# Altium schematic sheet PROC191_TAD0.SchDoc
size 431 x 279 mm; Date: Not shown in title block; ApprovedBy: Not shown in title block; CheckedBy: Not shown in title block; Author: Not shown in title block; CompanyName: Not shown in title block; Engineer: Not shown in title block; Organization: Not shown in title block; Address1: Not shown in title block; Address2: Not shown in title block; Address3: Not shown in title block; Address4: Not shown in title block; DocumentNumber: 4; Revision: Use project parameter SCH_Rev; SheetNumber: 6; SheetTotal: 8; PageSetup: Record=PageOptions¦CenterHorizontal=True¦CenterVertical=True¦PrintScale=1.00¦XCorrection=1.00¦YCorrection=1.00¦PrintKind=0¦BorderSize=5000000¦LeftOffset=0¦BottomOffset=0¦Orientation=2¦PaperLength=1000¦PaperWidth=1000¦Scale=100¦PaperSource=15¦PrintQuality=600¦MediaType=1¦DitherType=10¦PaperKind=Letter¦PrintScaleMode=1
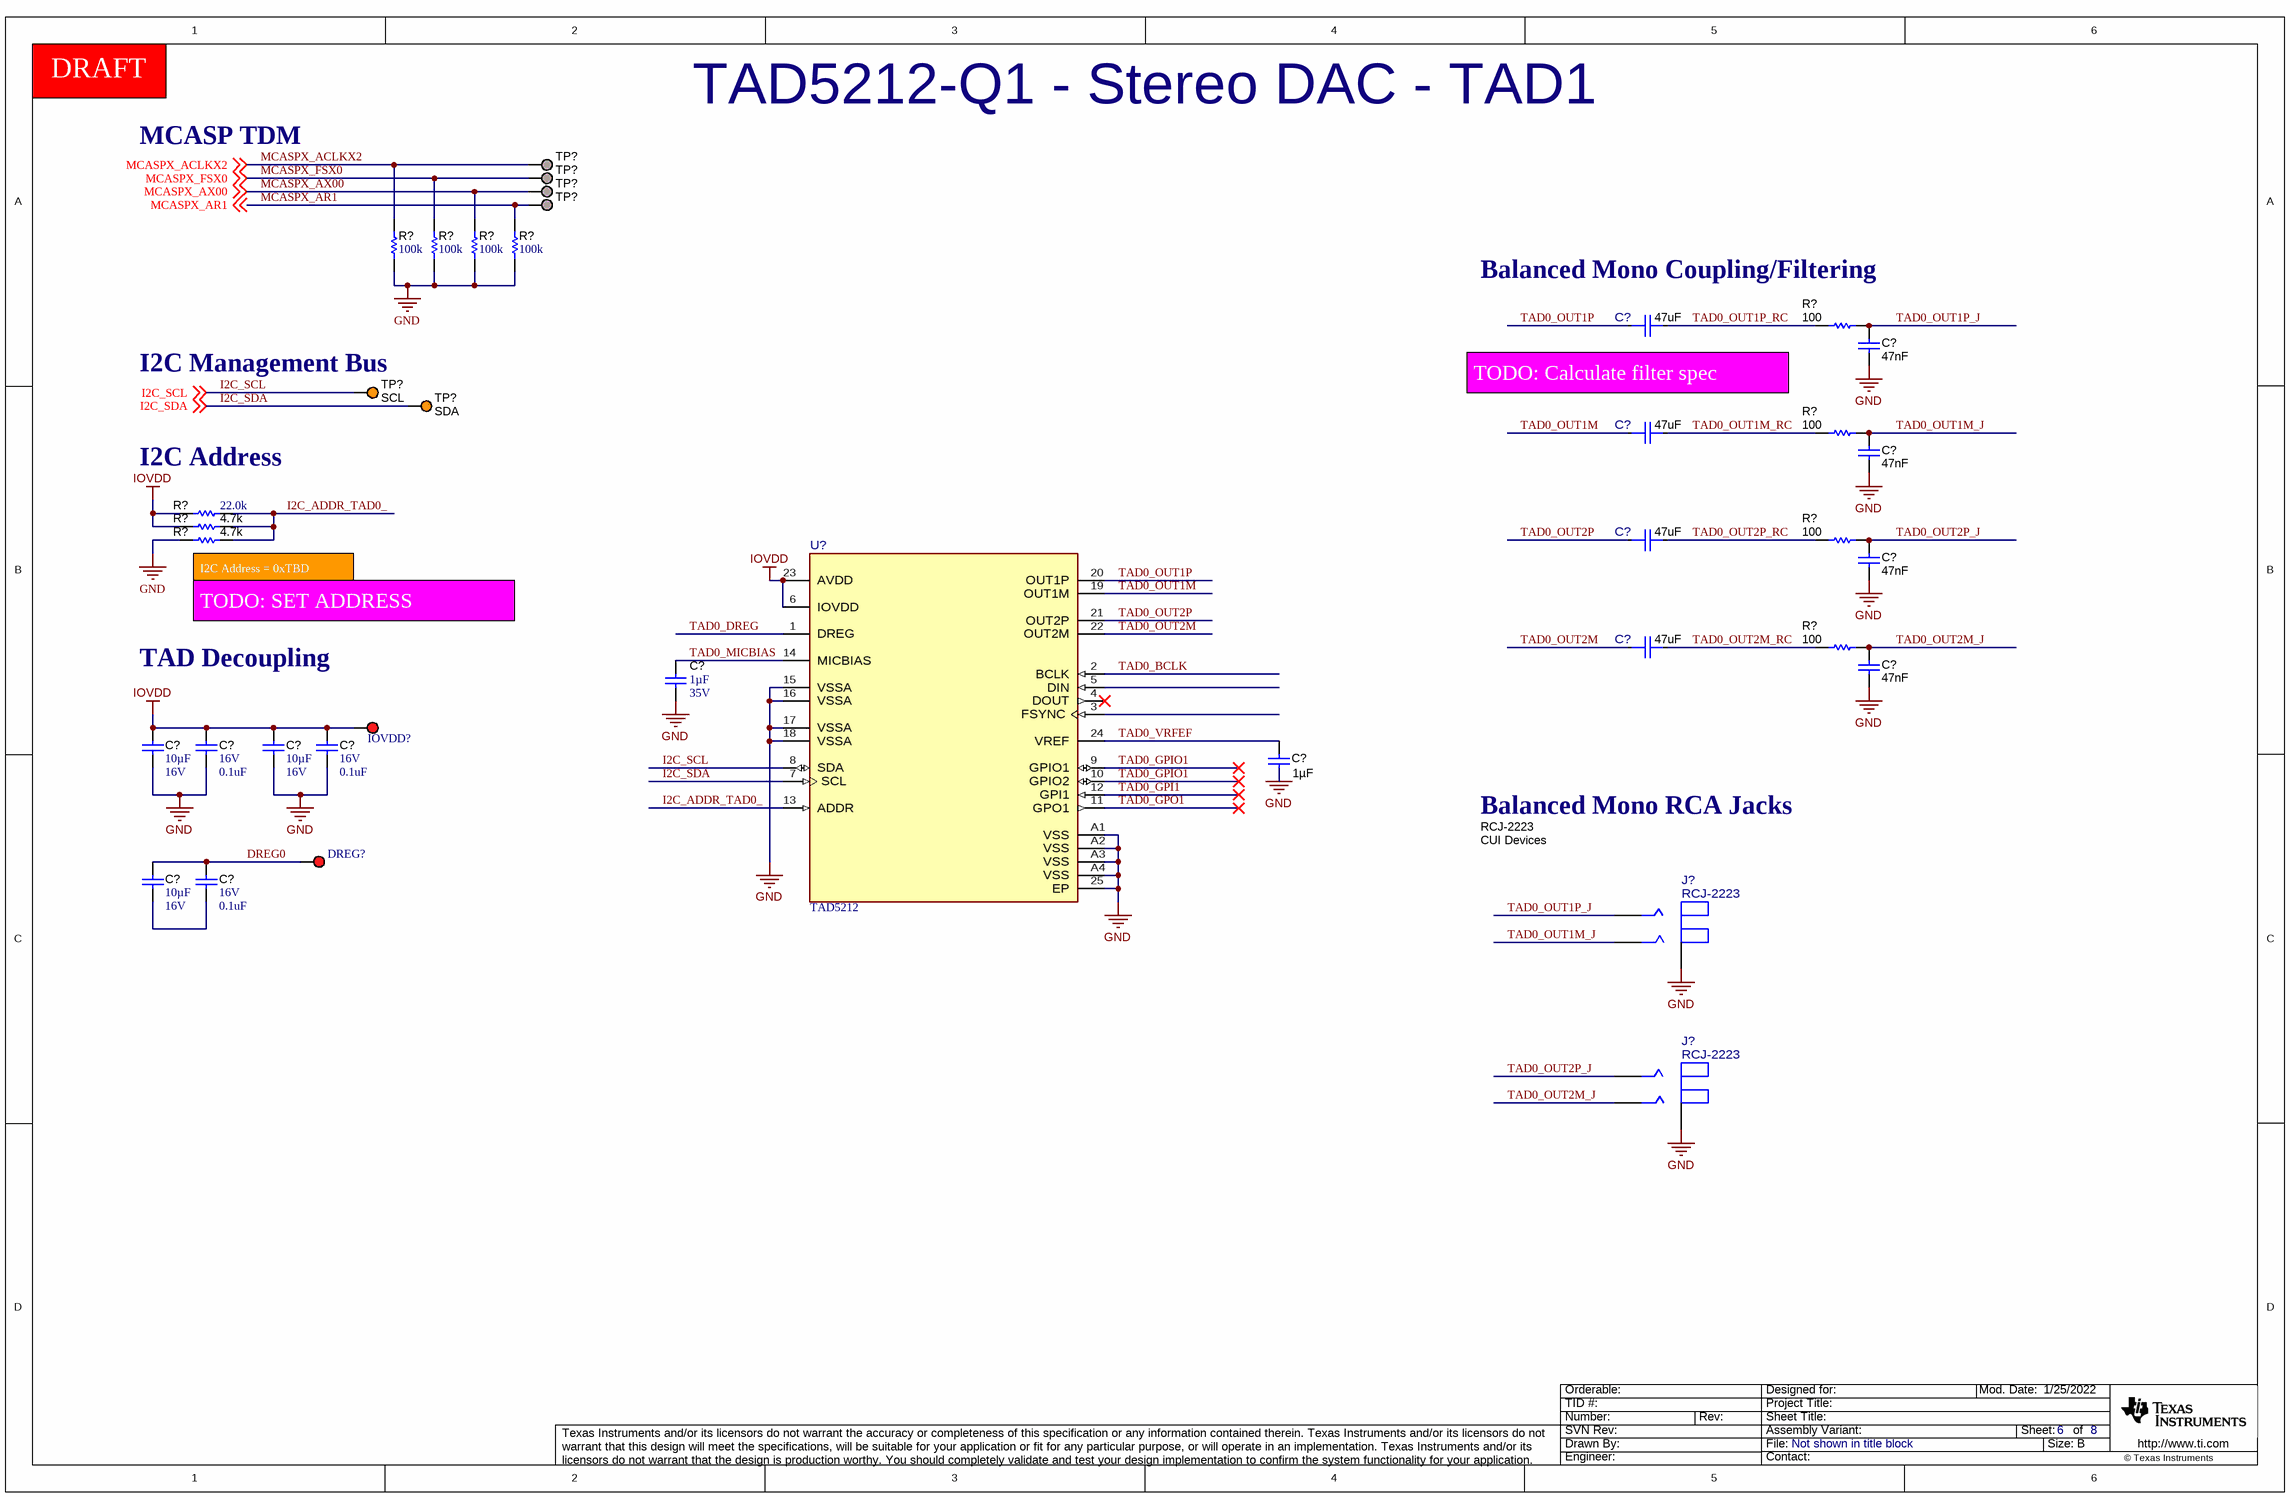
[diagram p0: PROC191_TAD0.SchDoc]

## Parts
(Parts that share a designator on the sheet are numbered #1, #2 ... from top to bottom, then left to right.)
C?#1  ValueDisplayed: 47uF  [FP-GRT32EC81C476KE13L_1210-MFG]  (hidden comment: GRT32EC81C476KE13L)
C?#2  Cap_F: 47nF  [0603]  (hidden comment: C1608X7R1H473K080AA)
C?#3  ValueDisplayed: 47uF  [FP-GRT32EC81C476KE13L_1210-MFG]  (hidden comment: GRT32EC81C476KE13L)
C?#4  Cap_F: 47nF  [0603]  (hidden comment: C1608X7R1H473K080AA)
C?#5  ValueDisplayed: 47uF  [FP-GRT32EC81C476KE13L_1210-MFG]  (hidden comment: GRT32EC81C476KE13L)
C?#6  Cap_F: 47nF  [0603]  (hidden comment: C1608X7R1H473K080AA)
C?#7  ValueDisplayed: 47uF  [FP-GRT32EC81C476KE13L_1210-MFG]  (hidden comment: GRT32EC81C476KE13L)
C?#8  Cap_F: 47nF  [0603]  (hidden comment: C1608X7R1H473K080AA)
C?#9  Cap_F: 1µF  VDC_V: 35V  [0603]  (hidden comment: C1608X7R1V105K080AC)
C?#10  Cap_F: 10µF  VDC_V: 16V  [0805_HV]  (hidden comment: EMK212BB7106KG-T)
C?#11  VDC_V: 16V  ValueDisplayed: 0.1uF  [0402]  (hidden comment: 885012205037)
C?#12  Cap_F: 10µF  VDC_V: 16V  [0805_HV]  (hidden comment: EMK212BB7106KG-T)
C?#13  VDC_V: 16V  ValueDisplayed: 0.1uF  [0402]  (hidden comment: 885012205037)
C?#14  Cap_F: 1µF  [0603]  (hidden comment: 885012206052)
C?#15  Cap_F: 10µF  VDC_V: 16V  [0805_HV]  (hidden comment: EMK212BB7106KG-T)
C?#16  VDC_V: 16V  ValueDisplayed: 0.1uF  [0402]  (hidden comment: 885012205037)
DREG?  5000  [Keystone5000]  (value not drawn)
IOVDD?  5000  [Keystone5000]  (value not drawn)
J?#1  RCJ-2223  Manufacturer: CUI Devices  [FP-RCJ-2223_CONN_RCA_DUAL-0]
J?#2  RCJ-2223  [FP-RCJ-2223_CONN_RCA_DUAL-0]
R?#1  ValueDisplayed: 100k  [0402]  (hidden comment: RMCF0402FT100K)
R?#2  ValueDisplayed: 100k  [0402]  (hidden comment: RMCF0402FT100K)
R?#3  ValueDisplayed: 100k  [0402]  (hidden comment: RMCF0402FT100K)
R?#4  ValueDisplayed: 100k  [0402]  (hidden comment: RMCF0402FT100K)
R?#5  ValueDisplayed: 100  [0603]  (hidden comment: RC0603FR-07100RL)
R?#6  ValueDisplayed: 100  [0603]  (hidden comment: RC0603FR-07100RL)
R?#7  ValueDisplayed: 22.0k  [0603]  (hidden comment: RG1608P-223-B-T5)
R?#8  Res_ohm: 4.7k  [0603]  (hidden comment: ERJ-3GEYJ472V)
R?#9  Res_ohm: 4.7k  [0603]  (hidden comment: ERJ-3GEYJ472V)
R?#10  ValueDisplayed: 100  [0603]  (hidden comment: RC0603FR-07100RL)
R?#11  ValueDisplayed: 100  [0603]  (hidden comment: RC0603FR-07100RL)
TP?#1  AVDD  [TP_SM_1MM]  (value not drawn)  (no BOM)
TP?#2  AVDD  [TP_SM_1MM]  (value not drawn)  (no BOM)
TP?#3  AVDD  [TP_SM_1MM]  (value not drawn)  (no BOM)
TP?#4  AVDD  [TP_SM_1MM]  (value not drawn)  (no BOM)
TP?#5  SCL  [Keystone5003]
TP?#6  SDA  [Keystone5003]
U?  TAD5212  [RTW0024R-MFG]

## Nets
GND: C?#2.2 C?#4.2 C?#6.2 C?#8.2 C?#9.2 C?#10.2 C?#11.2 C?#12.2 C?#13.2 C?#14.2 J?#1.1 J?#2.1 R?#1.1 R?#2.1 R?#3.1 R?#4.1 R?#9.2 U?.15(VSSA) U?.16(VSSA) U?.17(VSSA) U?.18(VSSA) U?.25(EP) U?.A1(VSS) U?.A2(VSS) U?.A3(VSS) U?.A4(VSS)
IOVDD: C?#10.1 C?#11.1 C?#12.1 C?#13.1 IOVDD?.1 R?#7.1 R?#8.2 U?.6(IOVDD) U?.23(AVDD)
DREG0: C?#15.1 C?#16.1 DREG?.1
I2C_ADDR_TAD0_: R?#7.2 R?#8.1 R?#9.1 U?.13(ADDR)
I2C_SCL: TP?#5.1 U?.8(SDA) ; off-sheet I2C_SCL
I2C_SDA: TP?#6.1 U?.7(SCL) ; off-sheet I2C_SDA
MCASPX_ACLKX2: R?#1.2 TP?#1.1 ; off-sheet MCASPX_ACLKX2
MCASPX_AR1: R?#4.2 TP?#4.1 ; off-sheet MCASPX_AR1
MCASPX_AX00: R?#3.2 TP?#3.1 ; off-sheet MCASPX_AX00
MCASPX_FSX0: R?#2.2 TP?#2.1 ; off-sheet MCASPX_FSX0
TAD0_BCLK: U?.2(BCLK)
TAD0_DREG: U?.1(DREG)
TAD0_GPI1: U?.12(GPI1)
TAD0_GPIO1: U?.9(GPIO1) U?.10(GPIO2)
TAD0_GPO1: U?.11(GPO1)
TAD0_MICBIAS: C?#9.1 U?.14(MICBIAS)
TAD0_OUT1M: C?#3.1 U?.19(OUT1M)
TAD0_OUT1M_J: C?#4.1 J?#1.2 R?#6.2
TAD0_OUT1M_RC: C?#3.2 R?#6.1
TAD0_OUT1P: C?#1.1 U?.20(OUT1P)
TAD0_OUT1P_J: C?#2.1 J?#1.3 R?#5.2
TAD0_OUT1P_RC: C?#1.2 R?#5.1
TAD0_OUT2M: C?#7.1 U?.22(OUT2M)
TAD0_OUT2M_J: C?#8.1 J?#2.2 R?#11.2
TAD0_OUT2M_RC: C?#7.2 R?#11.1
TAD0_OUT2P: C?#5.1 U?.21(OUT2P)
TAD0_OUT2P_J: C?#6.1 J?#2.3 R?#10.2
TAD0_OUT2P_RC: C?#5.2 R?#10.1
TAD0_VRFEF: C?#14.1 U?.24(VREF)
NetC?#15_2: C?#15.2 C?#16.2

Not connected (* = marked no-connect by the designer): U? 3(FSYNC) 4(DOUT)* 5(DIN)

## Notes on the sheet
- DRAFT
- TAD5212-Q1 - Stereo DAC - TAD1
- MCASP TDM
- Balanced Mono Coupling/Filtering
- (near TP?#5) I2C Management Bus
- (near C?#1) TODO: Calculate filter spec
- (near R?#7) I2C Address
- (near R?#9) I2C Address = 0xTBD
- (near R?#9) TODO: SET ADDRESS
- TAD Decoupling
- Balanced Mono RCA Jacks

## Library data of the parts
C?#1 C?#3 C?#5 C?#7 = CMP-0088649-1: 47µF ±10% 16V Ceramic Capacitor X6S 1210 (3225 Metric); Manufacturer: Murata; AEC Grade: Grade 2; AEC Qualified: Yes; TempCo: 22%; SizeZ_mm: 2.7mm
C?#2 C?#4 C?#6 C?#8 = CMP-0007049-4: CAP, CERM, 0.047 uF, 50 V, +/- 10%, X7R, 0603; Manufacturer: TDK; TaMin_C: -55°C; ESR_ohm: 0.049007; Polarized: N; SizeAreaWB_mm2: 4.68; Value1: 0.049007 ohm; U/M: EA; TaMax_C: 125°C; SizeZ_mm: 1; SizeX_mm: 1.6; SizeY_mm: 0.8; Value2: 50V; SizeArea_mm2: 1.28; IRMS_A: 767.528mA; AEC Category: Q200
C?#9 = CMP-0007052-4: CAP, CERM, 1 uF, 35 V, +/- 10%, X7R, 0603; Manufacturer: TDK; TaMin_C: -55°C; Polarized: N; SizeAreaWB_mm2: 4.68; Value1: Unknown; U/M: EA; Value: 1uF; TaMax_C: 125°C; SizeZ_mm: 1; SizeX_mm: 1.6; SizeY_mm: 0.8; SizeArea_mm2: 1.28; AEC Category: Q200
C?#10 C?#12 C?#15 = CMP-0085283-1: CAP, CERM, 10 µF, 16 V,+/- 10%, X7R, 0805; Manufacturer: Taiyo Yuden; TaMin_C: -55°C; AEC Qualified: N; U/M: EA; TaMax_C: 125°C; SizeAreaWB_mm2: 6.75; SizeZ_mm: 1.45; Value: 10uF; SizeY_mm: 1.25; SizeArea_mm2: 2.5; AEC Category: Q200; SizeX_mm: 2; Cap_Case: 0805
C?#11 C?#13 C?#16 = CMP-0006228-2: CAP, CERM, 0.1 uF, 16 V, +/- 10%, X7R, 0402; Manufacturer: Wurth Elektronik; TaMin_C: -55°C; Polarized: N; SizeAreaWB_mm2: 3; Value1: Unknown; U/M: EA; Value: 0.1uF; TaMax_C: 125°C; SizeZ_mm: 0.6; SizeX_mm: 1; SizeY_mm: 0.5; Cap_F: 100nF; AEC Category: Q200
C?#14 = CMP-0006831-4: CAP, CERM, 1 uF, 16 V, +/- 10%, X7R, 0603; Manufacturer: Wurth Elektronik; TaMin_C: -55°C; Polarized: N; SizeAreaWB_mm2: 4.68; Value1: Unknown; U/M: EA; Value: 1uF; TaMax_C: 125°C; SizeZ_mm: 1; SizeX_mm: 1.6; SizeY_mm: 0.8; Value2: 16V; SizeArea_mm2: 1.28; AEC Category: Q200
DREG? IOVDD? = CMP-0055137-2: Test Point, Miniature, Red, TH; Manufacturer: Keystone Electronics; CNHeader: FALSE; Green_Lifecycle: Active; Green_REACh: Passed; ContactFinish: Silver; CT: TRUE
J?#1 = CMP-0094453-1: 3.20mm ID, 9.00mm OD (RCA) Phono (RCA) Jack Mono Connector Solder; Voltage_V: 24V; SizeZ_mm: 27.7mm; Conn Orientation: Horizontal; Current_A: 5A; ContactFinish: Tin,Nickel; DUT-Pitch_mm: 4mm; AEC Qualified: No
J?#2 = CMP-0094453-1: 3.20mm ID, 9.00mm OD (RCA) Phono (RCA) Jack Mono Connector Solder; Manufacturer: CUI Devices; Voltage_V: 24V; SizeZ_mm: 27.7mm; Conn Orientation: Horizontal; Current_A: 5A; ContactFinish: Tin,Nickel; DUT-Pitch_mm: 4mm; AEC Qualified: No
R?#1-R?#4 = CMP-0026753-1: RES, 100 k, 1%, 0.063 W, AEC-Q200 Grade 0, 0402; Manufacturer: Stackpole Electronics Inc; Power_W: 63mW; TempCo: 100 ppm/C; U/M: EA; Value: 100k; EIA_Code: E96; SizeX_mm: 1; SizeY_mm: 0.5; SizeZ_mm: 0.6; Value2: 0.063W; AEC Qualified: Y; VDC_V: 50V; AEC Grade: 0; AEC Category: Q200
R?#5 R?#6 R?#10 R?#11 = CMP-0022736-4: RES, 100, 1%, 0.1 W, 0603; Manufacturer: Yageo; Power_W: 100mW; TempCo: 100 ppm/C; Value_Code: 100R; Value: 100; EIA_Code: E96; SizeX_mm: 1.6; SizeY_mm: 0.8; SizeZ_mm: 1; Value2: 0.1W; SizeArea_mm2: 1.28; AEC Qualified: N; VDC_V: 75V; AEC Category: Q200; SizeAreaWB_mm2: 4.68
R?#7 = CMP-0023474-3: RES, 22.0 k, 0.1%, 0.1 W, 0603; Manufacturer: Susumu Co Ltd; Power_W: 100mW; TempCo: 25 ppm/C; Value_Code: 22k0; U/M: EA; Value: 22.0k; Res_ohm: 22k; SizeX_mm: 1.6; SizeY_mm: 0.8; SizeZ_mm: 1; Value2: 0.1W; SizeArea_mm2: 1.28; VDC_V: 75V; AEC Category: Q200
R?#8 R?#9 = CMP-0025881-3: RES, 4.7 k, 5%, 0.1 W, AEC-Q200 Grade 0, 0603; Manufacturer: Panasonic; Power_W: 100mW; TempCo: 200 ppm/C; Value_Code: 4k70; U/M: EA; Value: 4.7k; EIA_Code: E24; SizeX_mm: 1.6; SizeY_mm: 0.8; SizeZ_mm: 1; Value2: 0.1W; SizeArea_mm2: 1.28; AEC Qualified: Y; VDC_V: 75V; AEC Grade: 0; AEC Category: Q200
TP?#1-TP?#4 = CMP-0003825-1: 1mm Test Point, SMT; Manufacturer: Any
TP?#5 TP?#6 = CMP-0055140-1: Test Point, Miniature, Orange, TH; Manufacturer: Keystone; ContactFinish: Silver; CNHeader: FALSE; CT: TRUE; Green_Lifecycle: Active; Green_REACh: Passed
U? = CMP-0097345-3: High-performance stereo audio DAC with 115dB dynamic range DAC; Manufacturer: Texas Instruments; Number Of Converters: 2; TaMin_C: -40°C; Min Supply Voltage: 1.08V; TaMax_C: +125°C; SizeZ_mm: 0.8mm; Interface: I2C,SPI,I2S; Max Supply Voltage: 3.6V; AEC Category: Q200; TJmax_C: +150°C; AEC Qualified: No; Standoff Height: 0mm; Data Polarity: Differential; CompType: IC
